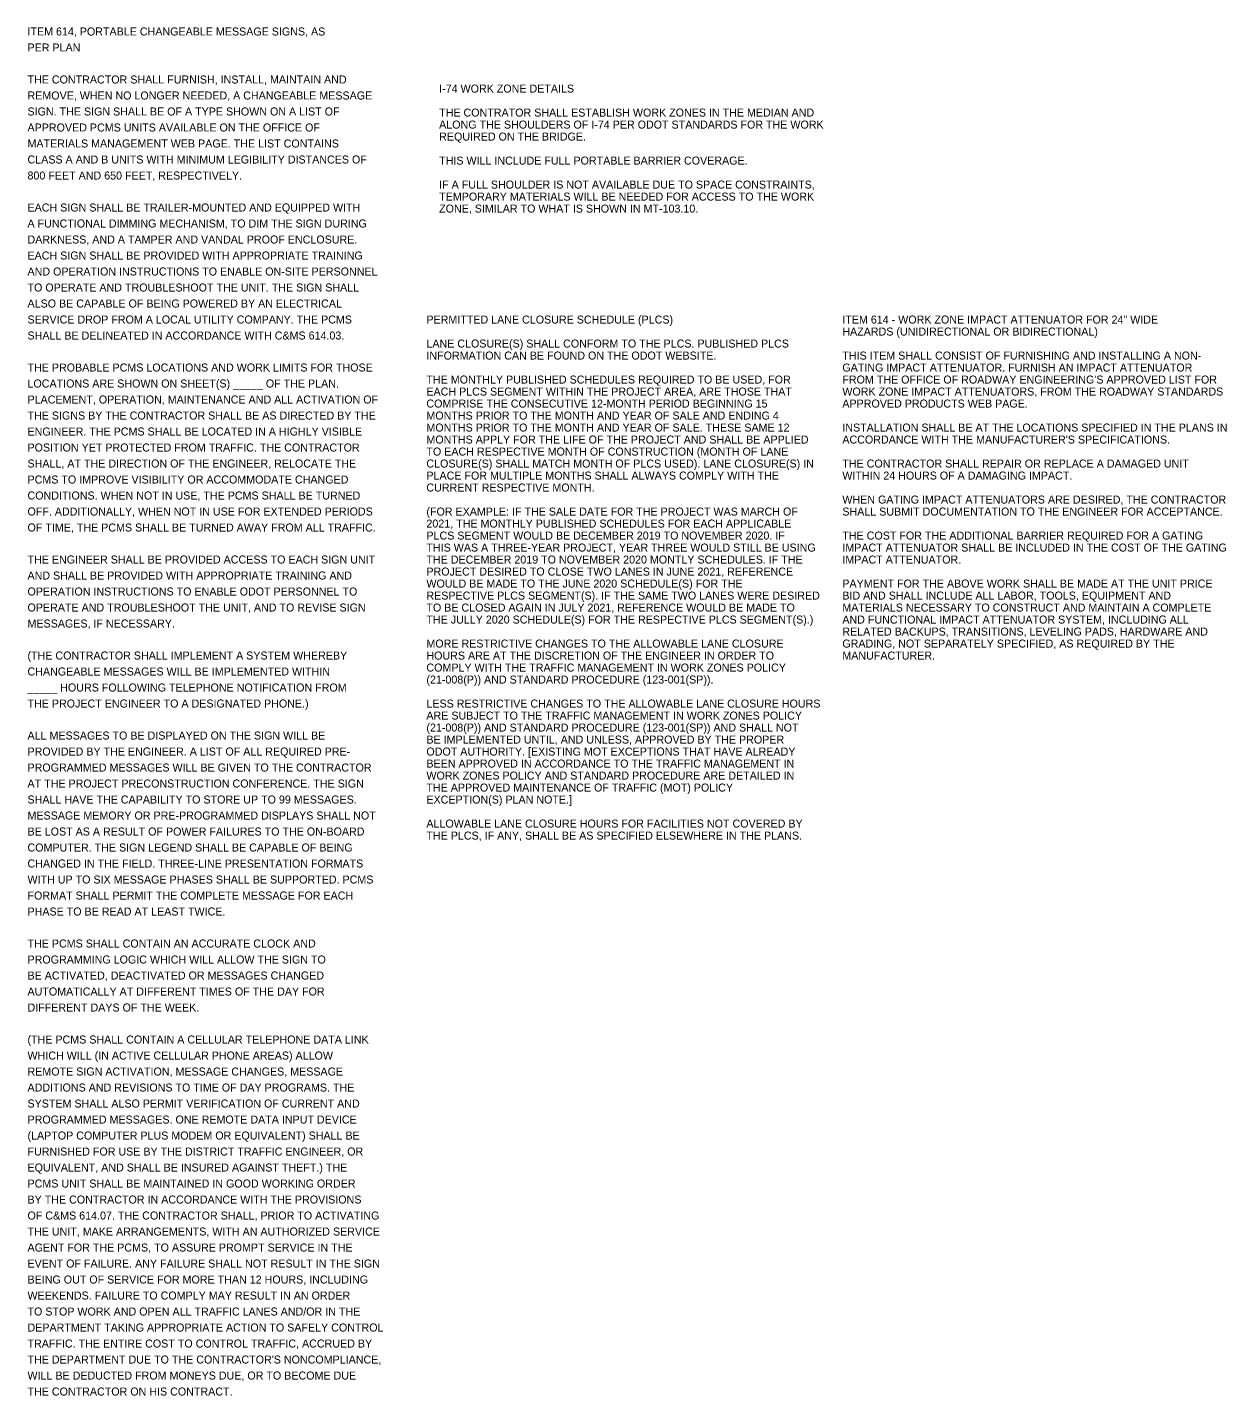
# Model space of a CAD drawing. Extents: x -65.5 to 34, y -24.3 to 23.1.
# Drawn here: x -43.1 to -22.11, y -0.83 to 23.12 of the extents above; entities that cross this region are included whole.
import ezdxf

# ---------------------------------------------------------------- set-up
doc = ezdxf.new("R2010")
doc.units = 0
doc.layers.add('SH_Text', color=7, linetype='Continuous')

msp = doc.modelspace()

# ---------------------------------------------------------------- texts
at = {"layer": 'SH_Text'}
for s, p in [('ITEM 614, PORTABLE CHANGEABLE MESSAGE SIGNS, AS', (-43.101, 22.976)), ('PER PLAN', (-43.101, 22.696)), ('THE CONTRACTOR SHALL FURNISH, INSTALL, MAINTAIN AND', (-43.101, 22.136)), ('I-74 WORK ZONE DETAILS', (-35.896, 21.977)), ('REMOVE, WHEN NO LONGER NEEDED, A CHANGEABLE MESSAGE', (-43.101, 21.856)), ('SIGN. THE SIGN SHALL BE OF A TYPE SHOWN ON A LIST OF', (-43.101, 21.576)), ('THE CONTRATOR SHALL ESTABLISH WORK ZONES IN THE MEDIAN AND ', (-35.896, 21.557)), ('APPROVED PCMS UNITS AVAILABLE ON THE OFFICE OF', (-43.101, 21.296)), ('ALONG THE SHOULDERS OF I-74 PER ODOT STANDARDS FOR THE WORK ', (-35.896, 21.347)), ('MATERIALS MANAGEMENT WEB PAGE. THE LIST CONTAINS', (-43.101, 21.016)), ('REQUIRED ON THE BRIDGE.', (-35.896, 21.137)), ('CLASS A AND B UNITS WITH MINIMUM LEGIBILITY DISTANCES OF', (-43.101, 20.736)), ('THIS WILL INCLUDE FULL PORTABLE BARRIER COVERAGE.', (-35.896, 20.717)), ('800 FEET AND 650 FEET, RESPECTIVELY.', (-43.101, 20.456)), ('IF A FULL SHOULDER IS NOT AVAILABLE DUE TO SPACE CONSTRAINTS, ', (-35.896, 20.297)), ('TEMPORARY MATERIALS WILL BE NEEDED FOR ACCESS TO THE WORK ', (-35.896, 20.087)), ('EACH SIGN SHALL BE TRAILER-MOUNTED AND EQUIPPED WITH', (-43.101, 19.896)), ('ZONE, SIMILAR TO WHAT IS SHOWN IN MT-103.10.', (-35.896, 19.877)), ('A FUNCTIONAL DIMMING MECHANISM, TO DIM THE SIGN DURING', (-43.101, 19.616)), ('DARKNESS, AND A TAMPER AND VANDAL PROOF ENCLOSURE.', (-43.101, 19.336)), ('EACH SIGN SHALL BE PROVIDED WITH APPROPRIATE TRAINING', (-43.101, 19.056)), ('AND OPERATION INSTRUCTIONS TO ENABLE ON-SITE PERSONNEL', (-43.101, 18.776)), ('TO OPERATE AND TROUBLESHOOT THE UNIT. THE SIGN SHALL', (-43.101, 18.496)), ('ALSO BE CAPABLE OF BEING POWERED BY AN ELECTRICAL', (-43.101, 18.216)), ('SERVICE DROP FROM A LOCAL UTILITY COMPANY. THE PCMS', (-43.101, 17.936)), ('PERMITTED LANE CLOSURE SCHEDULE (PLCS)', (-36.119, 17.935)), ('ITEM 614 - WORK ZONE IMPACT ATTENUATOR FOR 24" WIDE ', (-28.839, 17.935)), ('SHALL BE DELINEATED IN ACCORDANCE WITH C&MS 614.03.', (-43.101, 17.656)), ('HAZARDS (UNIDIRECTIONAL OR BIDIRECTIONAL)', (-28.839, 17.725)), ('LANE CLOSURE(S) SHALL CONFORM TO THE PLCS. PUBLISHED PLCS ', (-36.119, 17.515)), ('INFORMATION CAN BE FOUND ON THE ODOT WEBSITE.', (-36.119, 17.305)), ('THIS ITEM SHALL CONSIST OF FURNISHING AND INSTALLING A NON-', (-28.839, 17.305)), ('THE PROBABLE PCMS LOCATIONS AND WORK LIMITS FOR THOSE', (-43.101, 17.096)), ('THE MONTHLY PUBLISHED SCHEDULES REQUIRED TO BE USED, FOR ', (-36.119, 16.885)), ('GATING IMPACT ATTENUATOR. FURNISH AN IMPACT ATTENUATOR ', (-28.839, 17.095)), ("FROM THE OFFICE OF ROADWAY ENGINEERING'S APPROVED LIST FOR ", (-28.839, 16.885)), ('LOCATIONS ARE SHOWN ON SHEET(S) _____ OF THE PLAN.', (-43.101, 16.816)), ('EACH PLCS SEGMENT WITHIN THE PROJECT AREA, ARE THOSE THAT ', (-36.119, 16.675)), ('WORK ZONE IMPACT ATTENUATORS, FROM THE ROADWAY STANDARDS ', (-28.839, 16.675)), ('PLACEMENT, OPERATION, MAINTENANCE AND ALL ACTIVATION OF', (-43.101, 16.536)), ('COMPRISE THE CONSECUTIVE 12-MONTH PERIOD BEGINNING 15 ', (-36.119, 16.465)), ('APPROVED PRODUCTS WEB PAGE.', (-28.839, 16.465)), ('THE SIGNS BY THE CONTRACTOR SHALL BE AS DIRECTED BY THE', (-43.101, 16.256)), ('MONTHS PRIOR TO THE MONTH AND YEAR OF SALE AND ENDING 4 ', (-36.119, 16.255)), ('ENGINEER. THE PCMS SHALL BE LOCATED IN A HIGHLY VISIBLE', (-43.101, 15.976)), ('MONTHS PRIOR TO THE MONTH AND YEAR OF SALE. THESE SAME 12 ', (-36.119, 16.045)), ('INSTALLATION SHALL BE AT THE LOCATIONS SPECIFIED IN THE PLANS IN ', (-28.839, 16.045)), ('POSITION YET PROTECTED FROM TRAFFIC. THE CONTRACTOR', (-43.101, 15.696)), ('MONTHS APPLY FOR THE LIFE OF THE PROJECT AND SHALL BE APPLIED ', (-36.119, 15.835)), ("ACCORDANCE WITH THE MANUFACTURER'S SPECIFICATIONS.", (-28.839, 15.835)), ('TO EACH RESPECTIVE MONTH OF CONSTRUCTION (MONTH OF LANE ', (-36.119, 15.625)), ('SHALL, AT THE DIRECTION OF THE ENGINEER, RELOCATE THE', (-43.101, 15.416)), ('CLOSURE(S) SHALL MATCH MONTH OF PLCS USED). LANE CLOSURE(S) IN ', (-36.119, 15.415)), ('PLACE FOR MULTIPLE MONTHS SHALL ALWAYS COMPLY WITH THE ', (-36.119, 15.205)), ('WITHIN 24 HOURS OF A DAMAGING IMPACT.', (-28.839, 15.205)), ('THE CONTRACTOR SHALL REPAIR OR REPLACE A DAMAGED UNIT ', (-28.839, 15.415)), ('PCMS TO IMPROVE VISIBILITY OR ACCOMMODATE CHANGED', (-43.101, 15.136)), ('CURRENT RESPECTIVE MONTH.', (-36.119, 14.995)), ('CONDITIONS. WHEN NOT IN USE, THE PCMS SHALL BE TURNED', (-43.101, 14.856)), ('WHEN GATING IMPACT ATTENUATORS ARE DESIRED, THE CONTRACTOR ', (-28.839, 14.785)), ('OFF. ADDITIONALLY, WHEN NOT IN USE FOR EXTENDED PERIODS', (-43.101, 14.576)), ('(FOR EXAMPLE: IF THE SALE DATE FOR THE PROJECT WAS MARCH OF ', (-36.119, 14.575)), ('SHALL SUBMIT DOCUMENTATION TO THE ENGINEER FOR ACCEPTANCE.', (-28.839, 14.575)), ('OF TIME, THE PCMS SHALL BE TURNED AWAY FROM ALL TRAFFIC.', (-43.101, 14.296)), ('2021, THE MONTHLY PUBLISHED SCHEDULES FOR EACH APPLICABLE ', (-36.119, 14.365)), ('PLCS SEGMENT WOULD BE DECEMBER 2019 TO NOVEMBER 2020. IF ', (-36.119, 14.155)), ('THE COST FOR THE ADDITIONAL BARRIER REQUIRED FOR A GATING ', (-28.839, 14.155)), ('THIS WAS A THREE-YEAR PROJECT, YEAR THREE WOULD STILL BE USING ', (-36.119, 13.945)), ('IMPACT ATTENUATOR SHALL BE INCLUDED IN THE COST OF THE GATING ', (-28.839, 13.945)), ('THE ENGINEER SHALL BE PROVIDED ACCESS TO EACH SIGN UNIT', (-43.101, 13.736)), ('THE DECEMBER 2019 TO NOVEMBER 2020 MONTLY SCHEDULES. IF THE ', (-36.119, 13.735)), ('PROJECT DESIRED TO CLOSE TWO LANES IN JUNE 2021, REFERENCE ', (-36.119, 13.525)), ('IMPACT ATTENUATOR.', (-28.839, 13.735)), ('AND SHALL BE PROVIDED WITH APPROPRIATE TRAINING AND', (-43.101, 13.456)), ('WOULD BE MADE TO THE JUNE 2020 SCHEDULE(S) FOR THE ', (-36.119, 13.315)), ('PAYMENT FOR THE ABOVE WORK SHALL BE MADE AT THE UNIT PRICE ', (-28.839, 13.315)), ('OPERATION INSTRUCTIONS TO ENABLE ODOT PERSONNEL TO', (-43.101, 13.176)), ('RESPECTIVE PLCS SEGMENT(S). IF THE SAME TWO LANES WERE DESIRED ', (-36.119, 13.105)), ('BID AND SHALL INCLUDE ALL LABOR, TOOLS, EQUIPMENT AND ', (-28.839, 13.105)), ('OPERATE AND TROUBLESHOOT THE UNIT, AND TO REVISE SIGN', (-43.101, 12.896)), ('TO BE CLOSED AGAIN IN JULY 2021, REFERENCE WOULD BE MADE TO ', (-36.119, 12.895)), ('MATERIALS NECESSARY TO CONSTRUCT AND MAINTAIN A COMPLETE ', (-28.839, 12.895)), ('MESSAGES, IF NECESSARY.', (-43.101, 12.616)), ('THE JULLY 2020 SCHEDULE(S) FOR THE RESPECTIVE PLCS SEGMENT(S).)', (-36.119, 12.685)), ('AND FUNCTIONAL IMPACT ATTENUATOR SYSTEM, INCLUDING ALL ', (-28.839, 12.685)), ('RELATED BACKUPS, TRANSITIONS, LEVELING PADS, HARDWARE AND ', (-28.839, 12.475)), ('MORE RESTRICTIVE CHANGES TO THE ALLOWABLE LANE CLOSURE ', (-36.119, 12.265)), ('GRADING, NOT SEPARATELY SPECIFIED, AS REQUIRED BY THE ', (-28.839, 12.265)), ('(THE CONTRACTOR SHALL IMPLEMENT A SYSTEM WHEREBY', (-43.101, 12.056)), ('COMPLY WITH THE TRAFFIC MANAGEMENT IN WORK ZONES POLICY ', (-36.119, 11.845)), ('HOURS ARE AT THE DISCRETION OF THE ENGINEER IN ORDER TO ', (-36.119, 12.055)), ('MANUFACTURER.', (-28.839, 12.055)), ('CHANGEABLE MESSAGES WILL BE IMPLEMENTED WITHIN', (-43.101, 11.776)), ('(21-008(P)) AND STANDARD PROCEDURE (123-001(SP)).', (-36.119, 11.635)), ('_____ HOURS FOLLOWING TELEPHONE NOTIFICATION FROM', (-43.101, 11.496)), ('THE PROJECT ENGINEER TO A DESIGNATED PHONE.)', (-43.101, 11.216)), ('LESS RESTRICTIVE CHANGES TO THE ALLOWABLE LANE CLOSURE HOURS ', (-36.119, 11.215)), ('ARE SUBJECT TO THE TRAFFIC MANAGEMENT IN WORK ZONES POLICY ', (-36.119, 11.005)), ('ALL MESSAGES TO BE DISPLAYED ON THE SIGN WILL BE', (-43.101, 10.656)), ('(21-008(P)) AND STANDARD PROCEDURE (123-001(SP)) AND SHALL NOT ', (-36.119, 10.795)), ('BE IMPLEMENTED UNTIL, AND UNLESS, APPROVED BY THE PROPER ', (-36.119, 10.585)), ('PROVIDED BY THE ENGINEER. A LIST OF ALL REQUIRED PRE-', (-43.101, 10.376)), ('ODOT AUTHORITY. [EXISTING MOT EXCEPTIONS THAT HAVE ALREADY ', (-36.119, 10.375)), ('BEEN APPROVED IN ACCORDANCE TO THE TRAFFIC MANAGEMENT IN ', (-36.119, 10.165)), ('PROGRAMMED MESSAGES WILL BE GIVEN TO THE CONTRACTOR', (-43.101, 10.096)), ('WORK ZONES POLICY AND STANDARD PROCEDURE ARE DETAILED IN ', (-36.119, 9.955)), ('AT THE PROJECT PRECONSTRUCTION CONFERENCE. THE SIGN', (-43.101, 9.816)), ('THE APPROVED MAINTENANCE OF TRAFFIC (MOT) POLICY ', (-36.119, 9.745)), ('SHALL HAVE THE CAPABILITY TO STORE UP TO 99 MESSAGES.', (-43.101, 9.536)), ('EXCEPTION(S) PLAN NOTE.]', (-36.119, 9.535)), ('MESSAGE MEMORY OR PRE-PROGRAMMED DISPLAYS SHALL NOT', (-43.101, 9.256)), ('BE LOST AS A RESULT OF POWER FAILURES TO THE ON-BOARD', (-43.101, 8.976)), ('ALLOWABLE LANE CLOSURE HOURS FOR FACILITIES NOT COVERED BY ', (-36.119, 9.115)), ('THE PLCS, IF ANY, SHALL BE AS SPECIFIED ELSEWHERE IN THE PLANS.', (-36.119, 8.905)), ('COMPUTER. THE SIGN LEGEND SHALL BE CAPABLE OF BEING', (-43.101, 8.696)), ('CHANGED IN THE FIELD. THREE-LINE PRESENTATION FORMATS', (-43.101, 8.416)), ('WITH UP TO SIX MESSAGE PHASES SHALL BE SUPPORTED. PCMS', (-43.101, 8.136)), ('FORMAT SHALL PERMIT THE COMPLETE MESSAGE FOR EACH', (-43.101, 7.856)), ('PHASE TO BE READ AT LEAST TWICE.', (-43.101, 7.576)), ('THE PCMS SHALL CONTAIN AN ACCURATE CLOCK AND', (-43.101, 7.016)), ('PROGRAMMING LOGIC WHICH WILL ALLOW THE SIGN TO', (-43.101, 6.736)), ('BE ACTIVATED, DEACTIVATED OR MESSAGES CHANGED', (-43.101, 6.456)), ('AUTOMATICALLY AT DIFFERENT TIMES OF THE DAY FOR', (-43.101, 6.176)), ('DIFFERENT DAYS OF THE WEEK.', (-43.101, 5.896)), ('(THE PCMS SHALL CONTAIN A CELLULAR TELEPHONE DATA LINK', (-43.101, 5.336)), ('WHICH WILL (IN ACTIVE CELLULAR PHONE AREAS) ALLOW', (-43.101, 5.056)), ('REMOTE SIGN ACTIVATION, MESSAGE CHANGES, MESSAGE', (-43.101, 4.776)), ('ADDITIONS AND REVISIONS TO TIME OF DAY PROGRAMS. THE', (-43.101, 4.496)), ('SYSTEM SHALL ALSO PERMIT VERIFICATION OF CURRENT AND', (-43.101, 4.216)), ('PROGRAMMED MESSAGES. ONE REMOTE DATA INPUT DEVICE', (-43.101, 3.936)), ('(LAPTOP COMPUTER PLUS MODEM OR EQUIVALENT) SHALL BE', (-43.101, 3.656)), ('FURNISHED FOR USE BY THE DISTRICT TRAFFIC ENGINEER, OR', (-43.101, 3.376)), ('EQUIVALENT, AND SHALL BE INSURED AGAINST THEFT.) THE', (-43.101, 3.096)), ('PCMS UNIT SHALL BE MAINTAINED IN GOOD WORKING ORDER', (-43.101, 2.816)), ('BY THE CONTRACTOR IN ACCORDANCE WITH THE PROVISIONS', (-43.101, 2.536)), ('OF C&MS 614.07. THE CONTRACTOR SHALL, PRIOR TO ACTIVATING', (-43.101, 2.256)), ('THE UNIT, MAKE ARRANGEMENTS, WITH AN AUTHORIZED SERVICE', (-43.101, 1.976)), ('AGENT FOR THE PCMS, TO ASSURE PROMPT SERVICE IN THE', (-43.101, 1.696)), ('EVENT OF FAILURE. ANY FAILURE SHALL NOT RESULT IN THE SIGN', (-43.101, 1.416)), ('BEING OUT OF SERVICE FOR MORE THAN 12 HOURS, INCLUDING', (-43.101, 1.136)), ('WEEKENDS. FAILURE TO COMPLY MAY RESULT IN AN ORDER', (-43.101, 0.856)), ('TO STOP WORK AND OPEN ALL TRAFFIC LANES AND/OR IN THE', (-43.101, 0.576)), ('DEPARTMENT TAKING APPROPRIATE ACTION TO SAFELY CONTROL', (-43.101, 0.296)), ('TRAFFIC. THE ENTIRE COST TO CONTROL TRAFFIC, ACCRUED BY', (-43.101, 0.016)), ("THE DEPARTMENT DUE TO THE CONTRACTOR'S NONCOMPLIANCE,", (-43.101, -0.264)), ('WILL BE DEDUCTED FROM MONEYS DUE, OR TO BECOME DUE', (-43.101, -0.544)), ('THE CONTRACTOR ON HIS CONTRACT.', (-43.101, -0.824))]:
    msp.add_text(s, height=0.14, dxfattribs=at).set_placement(p)

doc.saveas('drawing.dxf')
